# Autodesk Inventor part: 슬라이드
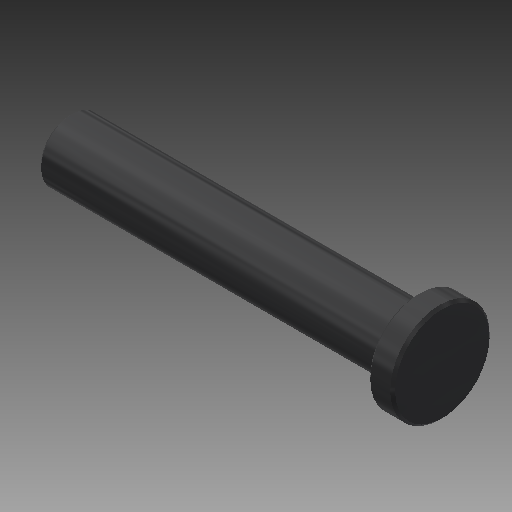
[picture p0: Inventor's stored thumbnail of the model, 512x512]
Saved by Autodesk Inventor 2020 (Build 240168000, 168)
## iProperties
Created: 2015-10
Part Number: 슬라이드
Document SubType Name: Modeling
Designer: mdu
Density: 1 g/cm^3
Material: 강철, 연강
Appearance: 진회색
Author: mdu
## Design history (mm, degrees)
sketch "스케치1"
  geometry: L1 (-75, 162)-(-75, 58) reference; L2 (-128, 110)-(22, 110); L3 (-128, 110)-(-128, 122.5); L4 (-128, 122.5)-(12, 122.5); L5 (12, 122.5)-(12, 130); L6 (12, 130)-(22, 130); L7 (22, 130)-(22, 110); 2 further points
  constraints: 12 end point, 3 parallel, 3 perpendicular, 1 midpoint, 1 point on line
  dimensions: "d0" = 40 diameter of L6 L2; "d1" = 25 diameter of L4 L2; "d2" = 10 distance of L5.end L6.end; "d3" = 150 distance of L2.start L2.end; "d4" = 53 distance between parallel lines of L3 L1
revolve "회전1" sketch "스케치1" stored, may be unused: angle "d5" = 90 deg
hole "구멍1" diameter "d11" = 10.106; stored, may be unused: countersink angle "d15" = 90 deg, drill point angle "d17" = 118 deg; dims "d12" = 22, "d13" = 4, "d14" = 2, "d16" = 25, "d18" = 10, "d19" = 10
chamfer "모따기1" distance "d6" = 1; stored, may be unused: second distance "d7" = 2, angle "d8" = 45 deg
node "솔리드1"
node "참조1"
